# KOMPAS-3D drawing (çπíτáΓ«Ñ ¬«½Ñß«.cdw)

Referenced files: Рабочие чертежи.cdw
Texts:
  ПЛК.721483.01
  Колесо тихоходное
  Noncommercial version
  Модуль нормальный
  Число зубьев
  Угол наклона зуба
  Symbol type A
  Направление зуба
  Исходный контур
  ГОСТ 13755-81
  Коэффициент смещения
  исходного контура
  Степень точности
  по ГОСТ 1643-81
  Делительный диаметр
  Tермообработка НВ190...210 - улучшение
  Неуказанные радиусы R3 max.
  Острые кромки притупить фаской
  Неуказанные предельные отклонения размеров
  отверстий H14, валов h14,остальное   0.5IT14
  @Arial Unicode MS
  Ra 1.6
  Ra 3.2
  Ra 25
  R0.4 max
  Ra12.5
  Ra6.3
  gost6_RGB_255_128_0_SC_1_THICK_0.15
  ACAD_ISO10W100_RGB_255_128_0_SC_0.5_THICK_0.15
  ACAD_ISO03W100_RGB_0_0_255_SC_0.25_THICK_0.5
  ACAD_ISO10W100_RGB_255_128_0_SC_0.75_THICK_0.15
  ACAD_ISO10W100_RGB_255_128_0_SC_1_THICK_0.15
  ACAD_ISO03W100_RGB_0_0_255_SC_0.15_THICK_0.5
  ACAD_ISO03W100_RGB_0_0_255_SC_0.25_THICK_0.53
  ACAD_ISO10W100_RGB_255_63_0_SC_0.5_THICK_0.15
  ACAD_ISO10W100_RGB_255_63_0_SC_1_THICK_0.15
  Стили документа
  Колесо
  тихоходное
  Сталь 45
  ГОСТ 1050-88
  РЧЦД.100/160.00.04-
  Вавилин В.В
Dimensions and other numbers on the sheet: 2,5; 89; 29 53; 0; 8-С; 256,58; 1.6; 0,8; 0.016; 120; 231; 261,6; 250,58; 176; 75; 0.05; 79,9; 20; 0.040; 0.100; 4 фаски; 30; 4 отв.; 40; 12; 100; 3.2; 25; 1; 1:1; 2; 3; 4; 5; 6; 7; 8; 9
